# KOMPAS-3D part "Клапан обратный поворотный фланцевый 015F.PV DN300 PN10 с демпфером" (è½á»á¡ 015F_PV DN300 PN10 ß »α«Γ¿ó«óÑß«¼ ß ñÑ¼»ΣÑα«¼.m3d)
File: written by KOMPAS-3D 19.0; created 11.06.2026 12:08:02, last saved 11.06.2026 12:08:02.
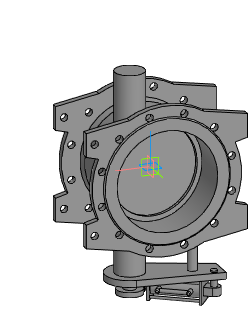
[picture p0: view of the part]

Document properties: Автор: Энергия; Полное имя файла: Z:\3.Личные\kachalov\001_3d для проектировщиков\5.5 Тип 015F.PV Клапан обратный поворотный с двумя эксцентриками\_stp_Клапан 015F.PV DN300-DN1200 с противовесом с демпфером\Клапан 015F_PV DN300 PN10 с противовесом с демпфером.m3d

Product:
- Part/product: Клапан обратный поворотный фланцевый 015F.PV DN300 PN10 с демпфером

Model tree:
1. Операция без истории:1
2. Сплайн:1
     Координата Y = 30; Координата Z = 150; Вес = 1; Координата X = 300; Координата Y = 69.4957; Координата Z = 150; Вес = 0.333333; Координата X = 300; Координата Y = 69.4957; Координата Z = -150; Вес = 0.333333; Координата Y = 30; Координата Z = -150; Вес = 1; Координата X = -300; Координата Y = -9.49575; Координата Z = -150; Вес = 0.333333; Координата X = -300; Координата Y = -9.49575; Координата Z = 150; Вес = 0.333333; Порядок = 4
